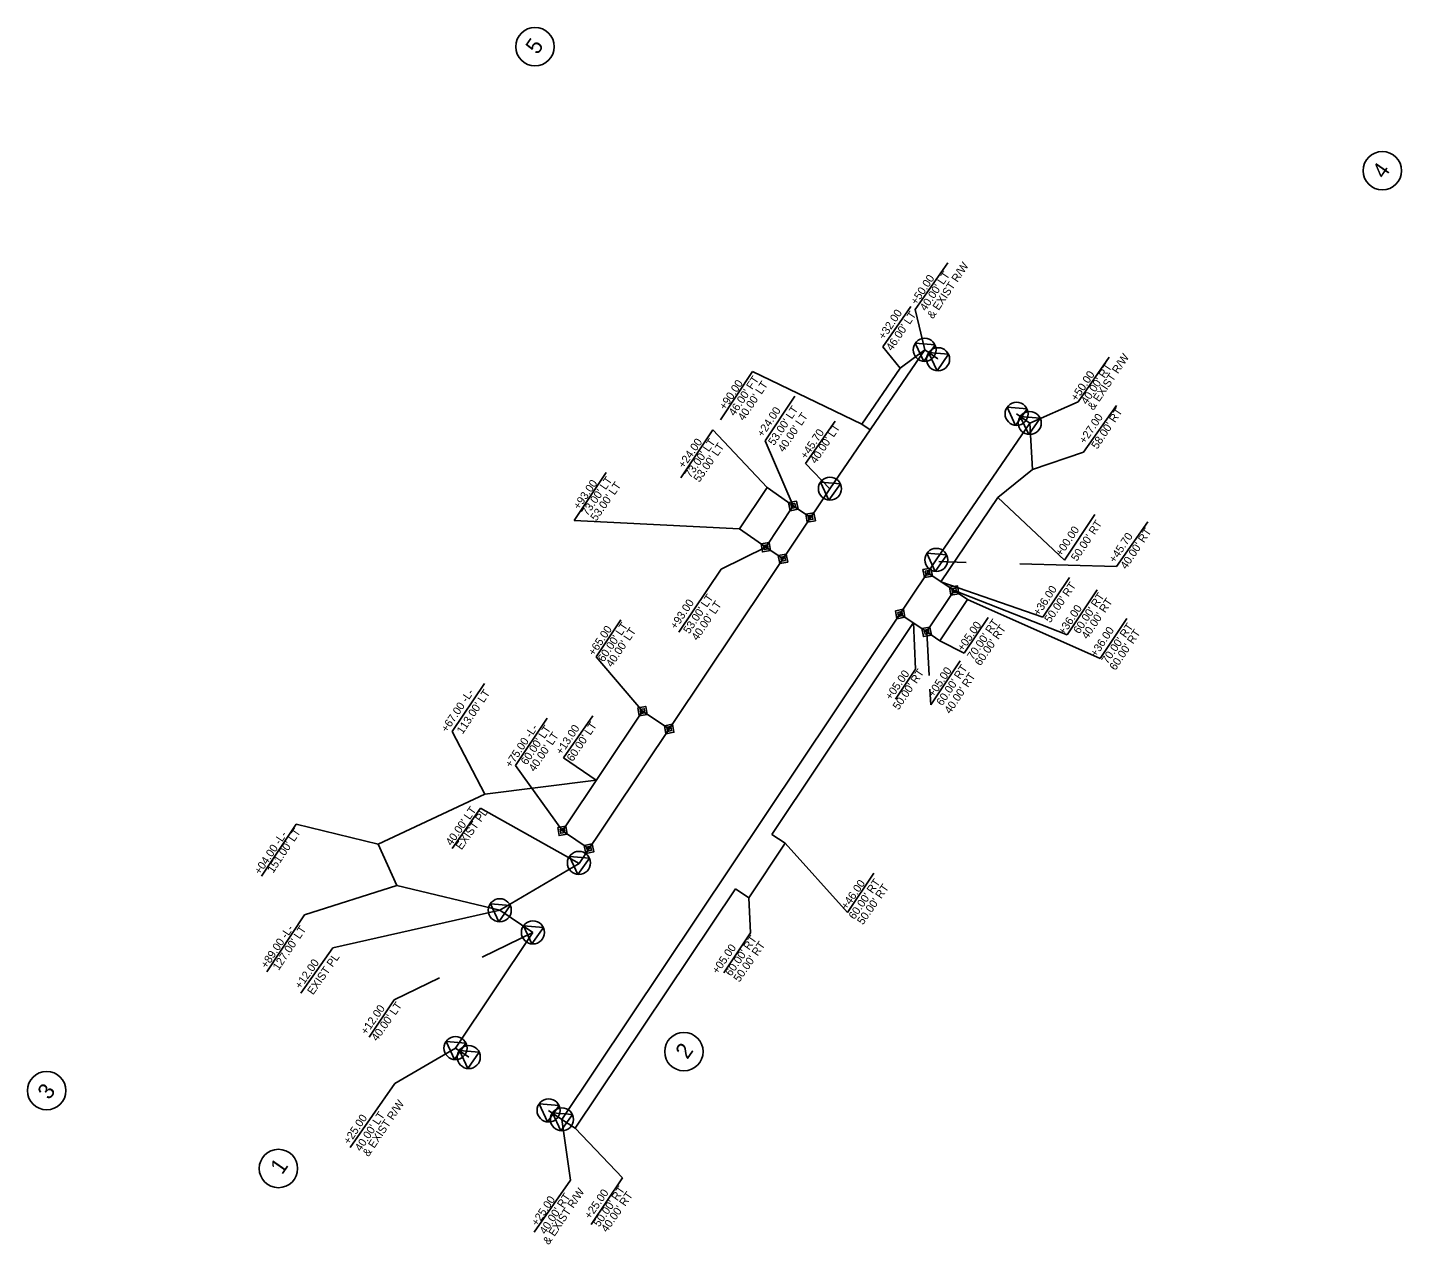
# Model space of a CAD drawing. Extents: x 1717120 to 1717979, y 800762 to 801523.
import ezdxf

# ---------------------------------------------------------------- set-up
doc = ezdxf.new("R2010")
doc.units = 0
for name, color, linetype in [('Exist Environmental Wetland Boundary', 7, 'Continuous'), ('Exist Environmental Wetland Boundary Cogo Comment', 7, 'Continuous'), ('Exist Environmental Wetland Boundary Cogo Elevation', 7, 'Continuous'), ('Exist Environmental Wetland Boundary Cogo Number', 7, 'Continuous'), ('Exist Environmental Wetland Boundary Cogo Point CELL', 7, 'Continuous'), ('Exist Hydro Jurisdictional Stream or Body of Water NEU Mitigable', 7, 'Continuous'), ('Exist Hydro Swamp or Marsh', 7, 'Continuous'), ('Prop Parcel Number CELL', 7, 'Continuous'), ('Prop Parcel Number Text', 7, 'Continuous'), ('Prop ROW Marker CELL', 7, 'Continuous')]:
    doc.layers.add(name, color=color, linetype=linetype)

msp = doc.modelspace()

# ---------------------------------------------------------------- linework, layer by layer
at = {"layer": 'Exist Environmental Wetland Boundary'}
for p, q in [((1717674.88, 801346.68), (1717695.29, 801375.89)), ((1717680.79, 801321.49), (1717674.88, 801346.68)), ((1717776.62, 801289.01), (1717796.18, 801316.99)), ((1717746.45, 801275.77), (1717776.62, 801289.01)), ((1717606.33, 801250.42), (1717624.89, 801276.99)), ((1717621.57, 801234.74), (1717606.33, 801250.42)), ((1717800.69, 801186.17), (1717820.15, 801214.01)), ((1717689.72, 801189.13), (1717706.66, 801188.68)), ((1717740.36, 801187.78), (1717800.69, 801186.17)), ((1717385.41, 801009.86), (1717403.11, 801035.17)), ((1717464.81, 801000.52), (1717403.11, 801035.17)), ((1717415.28, 800971.3), (1717310.85, 800947.84)), ((1717387.57, 800885.13), (1717435.96, 800957.43)), ((1717435.96, 800957.43), (1717404.3, 800942.04)), ((1717290.99, 800919.5), (1717310.85, 800947.84)), ((1717377.63, 800929.09), (1717349.34, 800915.35)), ((1717349.34, 800915.35), (1717333.71, 800891.99)), ((1717387.57, 800885.13), (1717349.6, 800863.03)), ((1717349.6, 800863.03), (1717321.65, 800823.05)), ((1717454.05, 800840.63), (1717459.48, 800802.68)), ((1717459.48, 800802.68), (1717436.71, 800770.1))]:
    msp.add_line(p, q, dxfattribs=at)
at = {"layer": 'Exist Environmental Wetland Boundary Cogo Comment'}
for p, q in [((1717581.46, 801198.18), (1717598.7, 801223.94)), ((1717609.5, 801216.71), (1717598.7, 801223.94)), ((1717581.46, 801198.18), (1717592.26, 801190.95)), ((1717682.66, 801182.18), (1717699.28, 801171.06)), ((1717682.03, 801145.28), (1717699.29, 801171.06)), ((1717665.42, 801156.42), (1717682.04, 801145.3)), ((1717454.38, 801020.91), (1717504.44, 801095.7)), ((1717521.07, 801084.58), (1717504.41, 801095.65)), ((1717471.01, 801009.78), (1717454.38, 801020.91))]:
    msp.add_line(p, q, dxfattribs=at)
at = {"layer": 'Exist Environmental Wetland Boundary Cogo Elevation'}
for points in [[(1717595.75, 801226), (1717600.76, 801226.89), (1717601.65, 801221.88), (1717596.64, 801220.99)], [(1717597.23, 801224.97), (1717599.73, 801225.42), (1717600.18, 801222.91), (1717597.67, 801222.46)], [(1717606.55, 801218.77), (1717611.57, 801219.66), (1717612.46, 801214.65), (1717607.44, 801213.76)], [(1717608.03, 801217.74), (1717610.54, 801218.18), (1717610.98, 801215.68), (1717608.47, 801215.23)], [(1717578.51, 801200.24), (1717583.52, 801201.13), (1717584.41, 801196.12), (1717579.4, 801195.23)], [(1717579.98, 801199.21), (1717582.49, 801199.65), (1717582.93, 801197.15), (1717580.43, 801196.7)], [(1717589.31, 801193.01), (1717594.32, 801193.9), (1717595.21, 801188.89), (1717590.2, 801188)], [(1717590.79, 801191.98), (1717593.29, 801192.42), (1717593.74, 801189.92), (1717591.23, 801189.47)], [(1717679.71, 801184.25), (1717684.73, 801185.13), (1717685.61, 801180.12), (1717680.6, 801179.23)], [(1717681.19, 801183.22), (1717683.69, 801183.66), (1717684.14, 801181.15), (1717681.63, 801180.71)], [(1717696.33, 801173.12), (1717701.35, 801174.01), (1717702.23, 801169), (1717697.22, 801168.11)], [(1717697.81, 801172.09), (1717700.31, 801172.53), (1717700.76, 801170.03), (1717698.25, 801169.58)], [(1717662.47, 801158.48), (1717667.48, 801159.37), (1717668.37, 801154.36), (1717663.36, 801153.47)], [(1717663.94, 801157.45), (1717666.45, 801157.9), (1717666.89, 801155.39), (1717664.39, 801154.95)], [(1717679.09, 801147.36), (1717684.1, 801148.25), (1717684.99, 801143.24), (1717679.98, 801142.35)], [(1717680.56, 801146.33), (1717683.07, 801146.77), (1717683.52, 801144.27), (1717681.01, 801143.82)], [(1717501.49, 801097.76), (1717506.51, 801098.65), (1717507.4, 801093.64), (1717502.38, 801092.75)], [(1717502.97, 801096.73), (1717505.48, 801097.17), (1717505.92, 801094.67), (1717503.41, 801094.22)], [(1717518.12, 801086.64), (1717523.13, 801087.53), (1717524.02, 801082.52), (1717519.01, 801081.63)], [(1717519.59, 801085.61), (1717522.1, 801086.06), (1717522.54, 801083.55), (1717520.04, 801083.1)], [(1717451.43, 801022.97), (1717456.45, 801023.86), (1717457.34, 801018.84), (1717452.32, 801017.96)], [(1717452.91, 801021.94), (1717455.42, 801022.38), (1717455.86, 801019.88), (1717453.35, 801019.43)], [(1717468.06, 801011.84), (1717473.07, 801012.73), (1717473.96, 801007.72), (1717468.94, 801006.83)], [(1717469.53, 801010.81), (1717472.04, 801011.26), (1717472.48, 801008.75), (1717469.97, 801008.31)]]:
    msp.add_lwpolyline(points, close=True, dxfattribs=at)
at = {"layer": 'Exist Environmental Wetland Boundary Cogo Number'}
for p, q in [((1717665.52, 801310.01), (1717680.79, 801321.49)), ((1717641.57, 801275.1), (1717665.52, 801310.01)), ((1717646.73, 801271.59), (1717641.57, 801275.1)), ((1717726.53, 801229.29), (1717748.25, 801246.79)), ((1717565.06, 801209.64), (1717582.31, 801235.4)), ((1717598.7, 801223.94), (1717582.31, 801235.4)), ((1717690.97, 801176.62), (1717726.53, 801229.29)), ((1717581.46, 801198.18), (1717565.06, 801209.64)), ((1717690.35, 801139.74), (1717707.59, 801165.5)), ((1717707.59, 801165.5), (1717699.28, 801171.06)), ((1717585.29, 801018.73), (1717673.84, 801151.03)), ((1717690.35, 801139.74), (1717682.04, 801145.3)), ((1717405.89, 801043.74), (1717475.52, 801052.49)), ((1717339.27, 801012.52), (1717405.89, 801043.74)), ((1717593.6, 801013.16), (1717585.29, 801018.73)), ((1717339.27, 801012.52), (1717350.87, 800986.7)), ((1717570.8, 800979.09), (1717593.6, 801013.16)), ((1717350.87, 800986.7), (1717415.26, 800971.29)), ((1717462.37, 800835.07), (1717562.49, 800984.65)), ((1717570.8, 800979.09), (1717562.49, 800984.65)), ((1717454.05, 800840.63), (1717462.37, 800835.07))]:
    msp.add_line(p, q, dxfattribs=at)
at = {"layer": 'Exist Environmental Wetland Boundary Cogo Point CELL'}
for p, q in [((1717621.57, 801234.74), (1717680.8, 801321.49)), ((1717689, 801315.78), (1717680.8, 801321.49)), ((1717746.45, 801275.77), (1717738.24, 801281.5)), ((1717688.06, 801190.24), (1717746.45, 801275.77)), ((1717464.81, 801000.52), (1717621.57, 801234.74)), ((1717454.05, 800840.63), (1717688.06, 801190.24)), ((1717464.81, 801000.52), (1717415.28, 800971.3)), ((1717415.26, 800971.29), (1717435.96, 800957.43)), ((1717395.88, 800879.56), (1717387.57, 800885.13)), ((1717445.74, 800846.19), (1717454.05, 800840.63))]:
    msp.add_line(p, q, dxfattribs=at)
at = {"layer": 'Exist Hydro Jurisdictional Stream or Body of Water NEU Mitigable'}
for p, q in [((1717581.02, 801264.68), (1717599.67, 801292.55)), ((1717598.7, 801223.94), (1717581.02, 801264.68)), ((1717581.46, 801198.18), (1717553.58, 801184.43)), ((1717527.18, 801144.99), (1717553.58, 801184.43)), ((1717699.28, 801171.06), (1717769.85, 801143.5)), ((1717769.85, 801143.5), (1717788.57, 801171.47)), ((1717475.46, 801129.6), (1717490.98, 801152.79)), ((1717682.04, 801145.3), (1717683.55, 801118.02)), ((1717504.44, 801095.7), (1717475.46, 801129.6)), ((1717684.57, 801099.6), (1717703.04, 801127.18)), ((1717684.02, 801109.55), (1717684.57, 801099.6)), ((1717425.03, 801061.77), (1717444.8, 801091.32)), ((1717454.38, 801020.91), (1717425.03, 801061.77))]:
    msp.add_line(p, q, dxfattribs=at)
at = {"layer": 'Exist Hydro Swamp or Marsh'}
for p, q in [((1717654.58, 801323.36), (1717672.16, 801348.52)), ((1717665.52, 801310.01), (1717654.58, 801323.36)), ((1717573.25, 801307.87), (1717553.13, 801277.81)), ((1717641.57, 801275.1), (1717573.25, 801307.87)), ((1717780.12, 801257.46), (1717800.58, 801286.74)), ((1717548.42, 801271.52), (1717528.29, 801241.46)), ((1717582.31, 801235.4), (1717548.42, 801271.52)), ((1717748.25, 801246.79), (1717746.45, 801275.77)), ((1717748.25, 801246.79), (1717780.12, 801257.46)), ((1717481.76, 801244.91), (1717461.64, 801214.84)), ((1717768.12, 801190.08), (1717726.53, 801229.29)), ((1717768.12, 801190.08), (1717787.19, 801218.58)), ((1717565.06, 801209.64), (1717461.64, 801214.84)), ((1717690.97, 801176.62), (1717754.67, 801154.34)), ((1717754.67, 801154.34), (1717771.31, 801179.2)), ((1717707.59, 801165.5), (1717790.43, 801128.66)), ((1717673.84, 801151.03), (1717675.06, 801121.9)), ((1717705.5, 801131.92), (1717720.38, 801154.15)), ((1717790.43, 801128.66), (1717807.07, 801153.52)), ((1717690.35, 801139.74), (1717705.5, 801131.92)), ((1717675.06, 801121.9), (1717662.51, 801103.15)), ((1717405.71, 801113.02), (1717385.58, 801082.95)), ((1717455.08, 801066.62), (1717473.38, 801092.81)), ((1717405.89, 801043.74), (1717385.58, 801082.95)), ((1717475.52, 801052.49), (1717455.08, 801066.62)), ((1717288.04, 801025.06), (1717266.33, 800992.62)), ((1717339.27, 801012.52), (1717288.04, 801025.06)), ((1717593.6, 801013.16), (1717632.58, 800969.83)), ((1717632.58, 800969.83), (1717649.03, 800994.42)), ((1717350.87, 800986.7), (1717293.28, 800968.34)), ((1717570.8, 800979.09), (1717571.95, 800957.1)), ((1717293.28, 800968.34), (1717269.57, 800932.91)), ((1717415.28, 800971.3), (1717310.85, 800947.84)), ((1717571.95, 800957.1), (1717555.26, 800932.17)), ((1717290.99, 800919.5), (1717310.85, 800947.84)), ((1717462.37, 800835.07), (1717491.87, 800804.12)), ((1717491.87, 800804.12), (1717472.37, 800774.98))]:
    msp.add_line(p, q, dxfattribs=at)
at = {"layer": 'Prop Parcel Number CELL'}
for p, q in [((1717437.24, 801510.93), (1717437.24, 801510.93)), ((1717966.8, 801433.43), (1717966.8, 801433.43)), ((1717530.29, 800882.97), (1717530.29, 800882.97)), ((1717132.07, 800858.58), (1717132.07, 800858.58)), ((1717276.91, 800809.93), (1717276.91, 800809.93))]:
    msp.add_line(p, q, dxfattribs=at)
for centre in [(1717437.24, 801510.93), (1717966.8, 801433.43), (1717530.29, 800882.97), (1717132.07, 800858.58), (1717276.91, 800809.93)]:
    msp.add_circle(centre, 12, dxfattribs=at)
at = {"layer": 'Prop ROW Marker CELL'}
for p, q in [((1717680.79, 801321.49), (1717680.79, 801321.49)), ((1717689.15, 801315.65), (1717689.15, 801315.65)), ((1717738.24, 801281.5), (1717738.24, 801281.5)), ((1717746.45, 801275.77), (1717746.45, 801275.77)), ((1717621.57, 801234.74), (1717621.57, 801234.74)), ((1717598.7, 801223.94), (1717598.7, 801223.94)), ((1717609.5, 801216.71), (1717609.5, 801216.71)), ((1717581.46, 801198.18), (1717581.46, 801198.18)), ((1717592.26, 801190.95), (1717592.26, 801190.95)), ((1717688.06, 801190.24), (1717688.06, 801190.24)), ((1717682.66, 801182.18), (1717682.66, 801182.18)), ((1717699.28, 801171.06), (1717699.28, 801171.06)), ((1717665.42, 801156.42), (1717665.42, 801156.42)), ((1717682.04, 801145.3), (1717682.04, 801145.3)), ((1717504.44, 801095.7), (1717504.44, 801095.7)), ((1717521.07, 801084.58), (1717521.07, 801084.58)), ((1717454.38, 801020.91), (1717454.38, 801020.91)), ((1717471.01, 801009.78), (1717471.01, 801009.78)), ((1717464.68, 801000.86), (1717464.68, 801000.86)), ((1717415.26, 800971.29), (1717415.26, 800971.29)), ((1717435.96, 800957.43), (1717435.96, 800957.43)), ((1717387.57, 800885.13), (1717387.57, 800885.13)), ((1717395.88, 800879.56), (1717395.88, 800879.56)), ((1717445.75, 800846.19), (1717445.75, 800846.19)), ((1717454.06, 800840.63), (1717454.06, 800840.63))]:
    msp.add_line(p, q, dxfattribs=at)
for points in [[(1717680.16, 801314.3), (1717674.89, 801325.61), (1717687.32, 801324.55)], [(1717688.52, 801308.46), (1717683.25, 801319.77), (1717695.68, 801318.71)], [(1717737.61, 801274.31), (1717732.34, 801285.62), (1717744.77, 801284.56)], [(1717745.82, 801268.59), (1717740.54, 801279.9), (1717752.98, 801278.83)], [(1717620.95, 801227.56), (1717615.67, 801238.87), (1717628.11, 801237.8)], [(1717687.43, 801183.06), (1717682.16, 801194.37), (1717694.59, 801193.31)], [(1717464.05, 800993.67), (1717458.77, 801004.98), (1717471.21, 801003.92)], [(1717414.63, 800964.1), (1717409.36, 800975.41), (1717421.79, 800974.35)], [(1717435.33, 800950.24), (1717430.06, 800961.55), (1717442.49, 800960.49)], [(1717386.94, 800877.94), (1717381.67, 800889.25), (1717394.1, 800888.19)], [(1717395.25, 800872.38), (1717389.98, 800883.69), (1717402.41, 800882.62)], [(1717445.12, 800839), (1717439.85, 800850.31), (1717452.28, 800849.25)], [(1717453.43, 800833.44), (1717448.16, 800844.75), (1717460.59, 800843.69)]]:
    msp.add_lwpolyline(points, close=True, dxfattribs=at)
for centre in [(1717680.79, 801321.49), (1717689.15, 801315.65), (1717738.24, 801281.5), (1717746.45, 801275.77), (1717621.57, 801234.74), (1717688.06, 801190.24), (1717464.68, 801000.86), (1717415.26, 800971.29), (1717435.96, 800957.43), (1717387.57, 800885.13), (1717395.88, 800879.56), (1717445.75, 800846.19), (1717454.06, 800840.63)]:
    msp.add_circle(centre, 7.2, dxfattribs=at)

# ---------------------------------------------------------------- texts
at = {"layer": 'Exist Environmental Wetland Boundary'}
for s, rotation, p in [("40.00' LT", 56.20506, (1717681.43, 801345.32)), ('& EXIST R/W', 56.20506, (1717685.98, 801340.48)), ('+50.00', 56.20506, (1717675.69, 801349.17)), ('& EXIST R/W', 56.20506, (1717786.28, 801283.33)), ("40.00' RT", 56.20506, (1717782.13, 801286.93)), ('+50.00', 56.20506, (1717775.83, 801289.09)), ('+45.70', 56.20506, (1717606.74, 801252.78)), ("40.00' LT", 56.20506, (1717612.82, 801249.97)), ("40.00' RT", 56.20506, (1717806.78, 801184.01)), ('+45.70', 56.20506, (1717799.65, 801187.96)), ("40.00' LT", 55.04768, (1717385.05, 801011.22)), ('EXIST PL', 55.04768, (1717391.35, 801008.67)), ('EXIST PL', 55.04768, (1717298.56, 800918.06)), ('+12.00', 55.04768, (1717290.78, 800921.66)), ('+12.00', 55.04768, (1717331.94, 800893.08)), ("40.00' LT", 55.04768, (1717338.6, 800889.08)), ('& EXIST R/W', 56.20506, (1717333.22, 800816.94)), ('+25.00', 56.20506, (1717321.17, 800824.49)), ("40.00' LT", 56.20506, (1717328.34, 800820.25)), ('& EXIST R/W', 56.20506, (1717445.91, 800761.85)), ('+25.00', 56.20506, (1717438.66, 800773.5)), ("40.00' RT", 56.20506, (1717443.73, 800768.38))]:
    msp.add_text(s, height=5, rotation=rotation, dxfattribs=at).set_placement(p)
at = {"layer": 'Exist Environmental Wetland Boundary Cogo Number'}
msp.add_text("50.00' RT", height=5, rotation=56.20506, dxfattribs=at).set_placement((1717775.95, 801189.02))
at = {"layer": 'Exist Hydro Jurisdictional Stream or Body of Water NEU Mitigable'}
for s, p in [('+24.00', (1717579.63, 801266.56)), ("53.00' LT", (1717586.68, 801261.33)), ("40.00' LT", (1717592.7, 801257.16)), ('+93.00', (1717525.42, 801146.41)), ("53.00' LT", (1717533.62, 801143.67)), ("40.00' LT", (1717538.75, 801139.4)), ("60.00' RT", (1717777.38, 801143.62)), ("40.00' RT", (1717782.5, 801140.26)), ('+36.00', (1717767.93, 801142.9)), ('+65.00', (1717474.18, 801129.88)), ("60.00' LT", (1717480.2, 801126.06)), ("40.00' LT", (1717485.3, 801122.79)), ('+05.00', (1717686.47, 801104.04)), ("60.00' RT", (1717691.79, 801098.7)), ("40.00' RT", (1717696.79, 801093.66)), ("60.00' LT", (1717432.08, 801061.68)), ('+75.00 -L-', (1717422.21, 801059.96)), ("40.00' LT", (1717436.99, 801057.48))]:
    msp.add_text(s, height=5, rotation=56.20506, dxfattribs=at).set_placement(p)
at = {"layer": 'Exist Hydro Swamp or Marsh'}
for s, rotation, p in [('+50.00', 56.20506, (1717675.69, 801349.17)), ('+32.00', 56.20506, (1717655.5, 801327.5)), ("46.00' LT", 56.20506, (1717660.35, 801320.44)), ('+90.00', 56.20506, (1717556.05, 801283.5)), ("46.00' FT", 56.20506, (1717561.96, 801279.76)), ("40.00' LT", 56.20506, (1717567.7, 801276.78)), ('+50.00', 56.20506, (1717775.81, 801289.05)), ("58.00' RT", 56.20506, (1717788.66, 801259.09)), ('+27.00', 56.20506, (1717781, 801262.38)), ('+24.00', 55.04768, (1717530.29, 801247.03)), ("73.00' LT", 55.04768, (1717534.45, 801241.09)), ("53.00' LT", 55.04768, (1717539.95, 801238.38)), ("73.00' LT", 55.04768, (1717470.01, 801217.37)), ('+93.00', 55.04768, (1717464.76, 801221.23)), ("53.00' LT", 55.04768, (1717475.53, 801214.09)), ('+00.00', 56.20506, (1717766.19, 801192.02)), ('+36.00', 56.20506, (1717752.21, 801154.88)), ("50.00' RT", 55.04768, (1717759.21, 801150.52)), ('+05.00', 55.04768, (1717704.71, 801132.68)), ("70.00' RT", 55.04768, (1717710.94, 801127.38)), ("60.00' RT", 55.71094, (1717715.65, 801123.65)), ('+36.00', 56.20506, (1717787.97, 801129.2)), ("70.00' RT", 55.04768, (1717794.97, 801124.84)), ("60.00' RT", 56.20506, (1717799.96, 801120.78)), ("50.00' RT", 55.71094, (1717664.47, 801096.09)), ('+05.00', 55.04768, (1717659.74, 801102.26)), ('+67.00 -L-', 56.20506, (1717382.22, 801082.03)), ("113.00' LT", 56.20506, (1717392.01, 801080.96)), ('+13.00', 56.20506, (1717453.9, 801067.98)), ("60.00' LT", 56.20506, (1717460.78, 801063.81)), ('+04.00 -L-', 56.20506, (1717265.43, 800993.17)), ("151.00' LT", 56.20506, (1717273.6, 800994.11)), ('+46.00', 55.04768, (1717632.07, 800971.25)), ("60.00' RT", 55.04768, (1717636.86, 800965.1)), ("50.00' RT", 55.04768, (1717642.2, 800961.82)), ('+89.00 -L-', 56.20506, (1717269.51, 800934.53)), ("127.00' LT", 56.20506, (1717277.04, 800933.34)), ('+05.00', 55.1293, (1717551.47, 800931.01)), ("60.00' RT", 55.1293, (1717559.76, 800929.7)), ("50.00' RT", 55.04768, (1717564.94, 800926.01)), ('EXIST PL', 55.04768, (1717298.56, 800918.06)), ('+12.00', 55.04768, (1717290.78, 800921.66)), ('+25.00', 55.04768, (1717471.73, 800777.9)), ("50.00' RT", 55.04768, (1717477.31, 800773.06)), ("40.00' RT", 55.04768, (1717482.18, 800769.65))]:
    msp.add_text(s, height=5, rotation=rotation, dxfattribs=at).set_placement(p)
at = {"layer": 'Prop Parcel Number Text'}
for s, p in [('5', (1717438.8, 801505.48)), ('4', (1717967.93, 801427.79)), ('2', (1717532.45, 800877.65)), ('3', (1717133.77, 800852.36)), ('1', (1717279.22, 800805.58))]:
    msp.add_text(s, height=10, rotation=55.04768, dxfattribs=at).set_placement(p)

doc.saveas('drawing.dxf')
